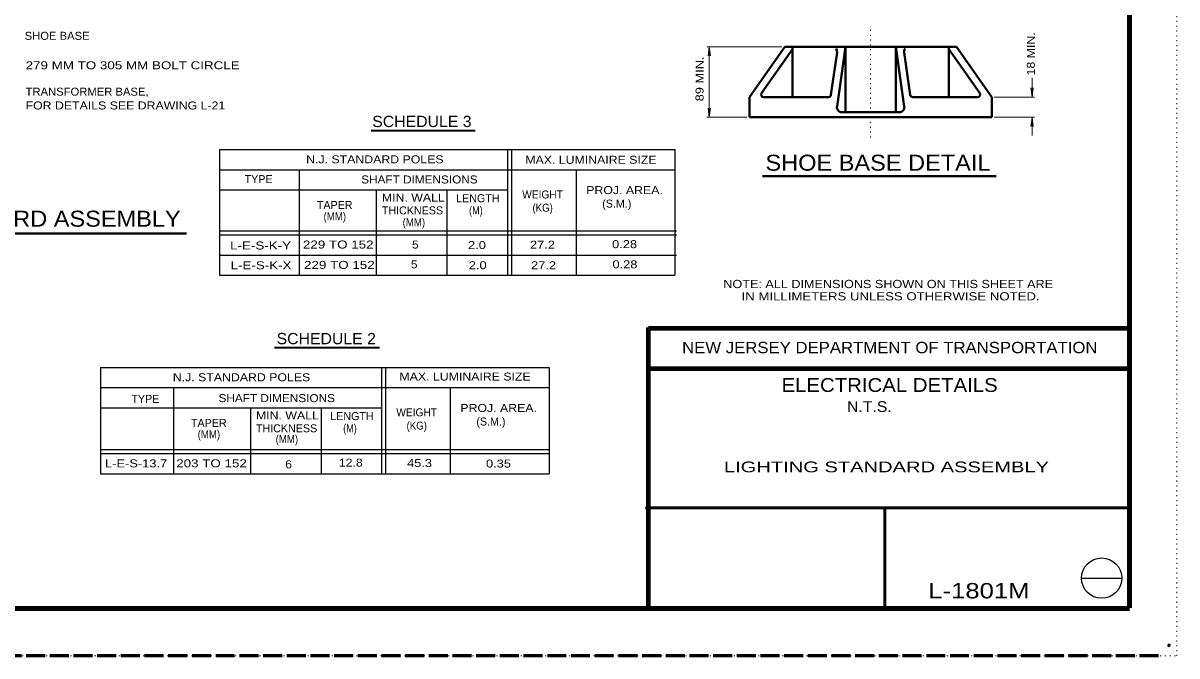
# Model space of a CAD drawing. Extents: x 312583 to 312854, y 144419 to 144597.
# Drawn here: x 312743.9 to 312853.5, y 144418.6 to 144478.7 of the extents above; entities that cross this region are included whole.
import ezdxf
from ezdxf.enums import TextEntityAlignment as Align

# ---------------------------------------------------------------- set-up
doc = ezdxf.new("R2010")
doc.units = 0
doc.header["$LTSCALE"] = 0.3
doc.header["$PDMODE"] = 32
doc.header["$PDSIZE"] = 0.15
doc.linetypes.add('DOTTED', pattern=[1.5, 0.3, -1.2])
doc.linetypes.add('LONG_DASHED', pattern=[7.5, 6, -1.5])
for name, color, linetype, lineweight in [('1', 7, 'Continuous', 40), ('10', 7, 'Continuous', 25), ('2', 7, 'Continuous', 13), ('63', 7, 'DOTTED', 13)]:
    doc.layers.add(name, color=color, linetype=linetype, lineweight=lineweight)
doc.layers.add('5', color=7, linetype='Continuous')

msp = doc.modelspace()

# ---------------------------------------------------------------- linework, layer by layer
at = {"layer": '1', "lineweight": 158}
for p, q in [((312849, 144423.1446), (312849, 144585.0846)), ((312616.5, 144423.0846), (312849, 144423.0846))]:
    msp.add_line(p, q, dxfattribs=at)
at = {"layer": '1'}
for p, q in [((312816.261, 144476.4902), (312812.9107, 144471.6986)), ((312816.9817, 144476.2679), (312814.053, 144472.0742)), ((312816.261, 144476.4902), (312824.4107, 144476.4902)), ((312816.9817, 144476.4902), (312816.9817, 144471.6986)), ((312821.2137, 144475.9459), (312820.6387, 144471.9056)), ((312822.011, 144476.4902), (312821.2137, 144470.8092)), ((312822.011, 144476.4902), (312822.011, 144470.2649)), ((312832.5527, 144476.4902), (312824.4107, 144476.4902)), ((312826.8027, 144476.4902), (312826.8027, 144470.2649)), ((312826.8027, 144476.4902), (312827.6077, 144470.8092)), ((312827.6077, 144475.9459), (312828.175, 144471.9056)), ((312831.8397, 144476.4902), (312831.8397, 144471.6986)), ((312831.8397, 144476.2679), (312834.7684, 144472.0742)), ((312832.5527, 144476.4902), (312835.9107, 144471.6986)), ((312812.9107, 144471.6986), (312812.9107, 144469.7819)), ((312814.2447, 144471.6986), (312820.4087, 144471.6986)), ((312834.5767, 144471.6986), (312828.4127, 144471.6986)), ((312835.9107, 144471.6986), (312835.9107, 144469.7819)), ((312821.689, 144470.2649), (312824.4107, 144470.2649)), ((312827.1324, 144470.2649), (312824.4107, 144470.2649)), ((312812.9107, 144469.7819), (312824.4107, 144469.7819)), ((312835.9107, 144469.7819), (312824.4107, 144469.7819))]:
    msp.add_line(p, q, dxfattribs=at)
at = {"layer": '1', "lineweight": 80}
for p, q in [((312803.31, 144423.1446), (312803.31, 144449.8146)), ((312803.31, 144449.7246), (312849, 144449.7246)), ((312803.31, 144445.9146), (312849, 144445.9146))]:
    msp.add_line(p, q, dxfattribs=at)
at = {"layer": '1', "lineweight": 53}
for p, q in [((312849, 144432.6666), (312803.0383, 144432.6666)), ((312825.7547, 144432.6666), (312825.7547, 144423.1446))]:
    msp.add_line(p, q, dxfattribs=at)
at = {"layer": '1'}
for centre, radius, start, end in [((312820.7775, 144476.0352), 0.4434, 348.38431, 37.0644), ((312828.0401, 144476.0352), 0.4434, 142.9356, 191.61569), ((312814.245, 144471.9382), 0.2396, 144.99918, 270), ((312820.4041, 144471.9382), 0.2396, 270, 351.97543), ((312828.4134, 144471.9382), 0.2396, 188.02457, 270), ((312834.5725, 144471.9382), 0.2396, 270, 35.00082), ((312821.6862, 144470.7402), 0.4792, 171.97543, 270), ((312827.1313, 144470.7402), 0.4792, 270, 8.02457)]:
    msp.add_arc(centre, radius, start, end, dxfattribs=at)
msp.add_point((312852.75, 144419.5846), dxfattribs=at)
at = {"layer": '10'}
msp.add_line((312844.4383, 144425.966), (312848.2793, 144425.966), dxfattribs=at)
msp.add_circle((312846.3494, 144425.9805), 1.9159, dxfattribs=at)
at = {"layer": '2', "linetype": 'DOTTED'}
msp.add_line((312824.4107, 144467.8652), (312824.4107, 144478.3072), dxfattribs=at)
at = {"layer": '2'}
for p, q in [((312815.962, 144476.4902), (312808.8397, 144476.4902)), ((312809.0774, 144476.4902), (312808.97, 144475.6239)), ((312808.97, 144475.6239), (312809.0774, 144475.8999)), ((312809.0774, 144469.7819), (312809.0774, 144476.4902)), ((312809.0774, 144476.4902), (312809.1847, 144475.6239)), ((312809.1847, 144475.6239), (312809.0774, 144475.8999)), ((312839.744, 144471.6986), (312839.744, 144473.5323)), ((312839.6367, 144472.5649), (312839.744, 144472.2889)), ((312839.744, 144471.6986), (312839.6367, 144472.5649)), ((312839.8514, 144472.5649), (312839.744, 144472.2889)), ((312839.744, 144471.6986), (312839.8514, 144472.5649)), ((312839.9817, 144471.6986), (312836.1484, 144471.6986)), ((312808.97, 144470.6482), (312809.0774, 144470.3722)), ((312809.0774, 144469.7819), (312808.97, 144470.6482)), ((312809.1847, 144470.6482), (312809.0774, 144470.3722)), ((312809.0774, 144469.7819), (312809.1847, 144470.6482)), ((312812.673, 144469.7819), (312808.8397, 144469.7819)), ((312839.9817, 144469.7819), (312836.1484, 144469.7819)), ((312839.744, 144469.7819), (312839.6367, 144468.9156)), ((312839.6367, 144468.9156), (312839.744, 144469.1916)), ((312839.744, 144468.0346), (312839.744, 144469.7819)), ((312839.744, 144469.7819), (312839.8514, 144468.9156)), ((312839.8514, 144468.9156), (312839.744, 144469.1916))]:
    msp.add_line(p, q, dxfattribs=at)
at = {"layer": '2', "lineweight": 35}
for p, q in [((312776.9639, 144468.5332), (312786.831, 144468.5332)), ((312767.7736, 144447.8944), (312777.7453, 144447.8944))]:
    msp.add_line(p, q, dxfattribs=at)
at = {"layer": '2', "lineweight": 25}
for p, q in [((312762.556, 144466.7086), (312762.556, 144454.7695)), ((312762.556, 144466.7086), (312805.8213, 144466.7086)), ((312789.9129, 144466.7086), (312789.9129, 144454.7695)), ((312790.2963, 144466.7086), (312790.2963, 144454.7695)), ((312805.8213, 144466.7086), (312805.8213, 144454.7695)), ((312762.556, 144464.7919), (312805.8213, 144464.7919)), ((312770.1389, 144464.7919), (312770.1389, 144454.7695)), ((312796.4296, 144464.7919), (312796.4296, 144454.7695)), ((312762.556, 144462.8752), (312789.9129, 144462.8752)), ((312777.4546, 144462.8752), (312777.4546, 144454.7695)), ((312784.1629, 144462.8752), (312784.1629, 144454.7695)), ((312762.556, 144458.9862), (312805.963, 144458.9862)), ((312762.556, 144458.6029), (312805.963, 144458.6029)), ((312762.556, 144456.6862), (312805.963, 144456.6862)), ((312762.556, 144454.7695), (312805.8213, 144454.7695)), ((312751.2718, 144445.999), (312793.8638, 144445.999)), ((312751.2718, 144445.999), (312751.2718, 144435.904)), ((312777.9555, 144445.999), (312777.9555, 144435.904)), ((312778.3388, 144445.999), (312778.3388, 144435.904)), ((312793.8638, 144445.999), (312793.8638, 144435.904)), ((312751.2718, 144444.0823), (312793.8638, 144444.0823)), ((312758.1815, 144444.0823), (312758.1815, 144435.904)), ((312784.4722, 144444.0823), (312784.4722, 144435.904)), ((312751.2718, 144442.1656), (312777.9555, 144442.1656)), ((312765.4972, 144442.1656), (312765.4972, 144435.904)), ((312772.2055, 144442.1656), (312772.2055, 144435.904)), ((312751.2718, 144438.204), (312793.8638, 144438.204)), ((312751.2718, 144437.8207), (312793.8638, 144437.8207)), ((312751.2718, 144435.904), (312793.8638, 144435.904))]:
    msp.add_line(p, q, dxfattribs=at)
at = {"layer": '2', "lineweight": 40}
for p, q in [((312814.1487, 144464.1852), (312836.3305, 144464.1852)), ((312722.1455, 144458.7223), (312759.4221, 144458.7223))]:
    msp.add_line(p, q, dxfattribs=at)
at = {"layer": '63', "linetype": 'LONG_DASHED', "lineweight": 60}
msp.add_line((312851.75, 144418.5846), (312583.526, 144418.5846), dxfattribs=at)
at = {"layer": '63'}
msp.add_lwpolyline([(312601.2, 144418.5846), (312853.5, 144418.5846), (312853.5, 144596.7846)], dxfattribs=at)

# ---------------------------------------------------------------- texts
at = {"layer": '1'}
for s, width, p in [('NOTE: ALL DIMENSIONS SHOWN ON THIS SHEET ARE', 1.15, (312810.4141, 144453.5448)), ('     IN MILLIMETERS UNLESS OTHERWISE NOTED.', 1.2, (312810.414, 144452.3748))]:
    msp.add_text(s, height=0.78, dxfattribs=dict(at, width=width)).set_placement(p)
at = {"layer": '1', "width": 1.1}
for s, height, p in [('NEW JERSEY DEPARTMENT OF TRANSPORTATION', 1.08, (312826.2285, 144447.3546)), ('ELECTRICAL DETAILS', 1.315, (312826.2109, 144443.676))]:
    msp.add_text(s, height=height, dxfattribs=at).set_placement(p, align=Align.CENTER)
at = {"layer": '2'}
for s, width, p in [('SHOE BASE', 1.05, (312744.054, 144477.1428)), ('279 MM TO 305 MM BOLT CIRCLE', 1.25, (312744.146, 144474.3417)), ('TRANSFORMER BASE,', 1.05, (312744.143, 144471.8346)), ('FOR DETAILS SEE DRAWING L-21', 1.15, (312744.143, 144470.5236)), ('N.J. STANDARD POLES', 1.15, (312770.7911, 144465.4004)), ('MAX. LUMINAIRE SIZE', 1.15, (312791.6073, 144465.3603)), ('SHAFT DIMENSIONS', 1.1, (312776.0233, 144463.4886)), ('WEIGHT', 0.95, (312791.3126, 144462.0654)), ('PROJ. AREA.', 1.15, (312797.3963, 144462.4795)), ('MIN. WALL', 1.15, (312777.9818, 144461.7713)), ('(KG)', 0.9, (312792.2892, 144460.8043)), ('(MM)', 0.9, (312772.4463, 144459.9887)), ('(M)', 0.85, (312786.2655, 144460.5561)), ('(MM)', 0.9, (312779.9584, 144459.4213)), ('L-E-S-K-Y', 1.25, (312763.5694, 144457.2142)), ('229 TO 152', 1.25, (312770.486, 144457.3053)), ('5 ', 1.1, (312780.8499, 144457.3053)), ('2.0 ', 1.2, (312786.1681, 144457.2546)), ('27.2 ', 1.2, (312792.0489, 144457.29)), ('0.28', 1.2, (312799.8496, 144457.3407)), ('L-E-S-K-X', 1.25, (312763.6124, 144455.3331)), ('229 TO 152', 1.25, (312770.5923, 144455.3685)), ('5 ', 1.1, (312780.7436, 144455.424)), ('2.0 ', 1.2, (312786.239, 144455.3378)), ('27.2 ', 1.2, (312792.1552, 144455.3378)), ('0.28', 1.2, (312799.885, 144455.424)), ('N.J. STANDARD POLES', 1.15, (312758.1266, 144444.6909)), ('MAX. LUMINAIRE SIZE', 1.15, (312779.6498, 144444.757)), ('SHAFT DIMENSIONS', 1.1, (312762.4712, 144442.7081)), ('MIN. WALL', 1.15, (312766.0244, 144441.0617)), ('WEIGHT', 0.95, (312779.3552, 144441.3558)), ('PROJ. AREA.', 1.15, (312785.4389, 144441.7699)), ('(KG)', 0.9, (312780.3318, 144440.0947)), ('(MM)', 0.9, (312760.4889, 144439.2791)), ('(MM)', 0.9, (312767.8947, 144438.8181)), ('(M)', 0.85, (312774.3081, 144439.8465)), ('L-E-S-13.7', 1.2, (312751.693, 144436.503)), ('203 TO 152', 1.25, (312758.4494, 144436.5106)), ('6 ', 1.15, (312768.7991, 144436.4167)), ('12.8 ', 1.15, (312773.8913, 144436.5787)), ('45.3 ', 1.2, (312780.3752, 144436.5433)), ('0.35', 1.2, (312787.8769, 144436.4877))]:
    msp.add_text(s, height=0.76, dxfattribs=dict(at, width=width)).set_placement(p)
for s, width, p in [('18 MIN.', 1.15, (312840.0041, 144473.7599)), ('89 MIN. ', 1.2, (312808.5357, 144471.2921))]:
    msp.add_text(s, height=0.76, rotation=90, dxfattribs=dict(at, width=width)).set_placement(p)
for s, height, width, p in [('SCHEDULE 3', 1.07, 1.05, (312781.7848, 144468.8511)), ('SHOE BASE DETAIL', 1.52, 1.1, (312825.1046, 144464.7028)), ('LIGHTING STANDARD ASSEMBLY', 1.52, 1.1, (312740.7958, 144459.3818)), ('SCHEDULE 2', 1.07, 1.05, (312772.7007, 144448.2123)), ('    N.T.S.  ', 1.02, 1.1, (312823.87, 144441.778)), ('         LIGHTING STANDARD ASSEMBLY         ', 1.02, 1.4, (312825.9119, 144436.04))]:
    msp.add_text(s, height=height, dxfattribs=dict(at, width=width)).set_placement(p, align=Align.CENTER)
for s, p in [('TYPE', (312764.9479, 144463.5241)), ('TAPER', (312771.8109, 144461.0619)), ('LENGTH', (312785.0395, 144461.7051)), ('(S.M.)', (312798.9154, 144461.1944)), ('THICKNESS', (312777.9818, 144460.5513)), ('TYPE', (312754.1968, 144442.6372)), ('LENGTH', (312773.0821, 144440.9955)), ('TAPER', (312759.8535, 144440.3523)), ('(S.M.)', (312786.958, 144440.4848)), ('THICKNESS', (312766.0244, 144439.8417))]:
    msp.add_text(s, height=0.76, dxfattribs=at).set_placement(p)
at = {"layer": '5', "width": 1.25}
msp.add_text('L-1801M  ', height=1.457, dxfattribs=at).set_placement((312835.3651, 144424.057), align=Align.CENTER)

doc.saveas('drawing.dxf')
